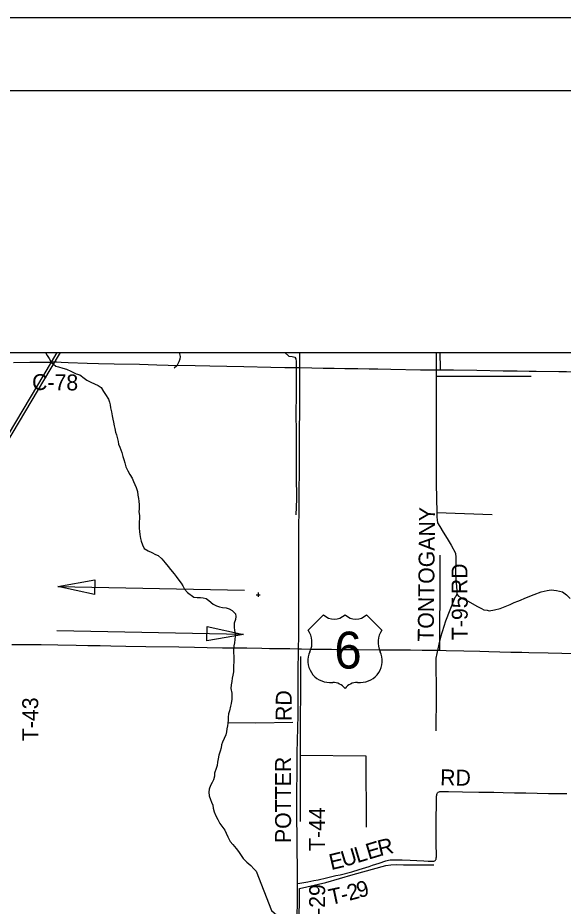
# Model space of a CAD drawing. Extents: x 0 to 680, y 0 to 834.
# Drawn here: x 113.1 to 187.9, y 318.1 to 440 of the extents above; entities that cross this region are included whole.
import ezdxf

# ---------------------------------------------------------------- set-up
doc = ezdxf.new("R2010")
doc.units = 0
for name, color, linetype in [('GM_X_County_Road', 7, 'Continuous'), ('GM_X_County_Road_Text', 7, 'Continuous'), ('GM_X_Interstate_Route', 7, 'Continuous'), ('GM_X_Minor_River', 7, 'Continuous'), ('GM_X_Rail_Line', 7, 'Continuous'), ('GM_X_Township_Road', 7, 'Continuous'), ('GM_X_Township_Road_Text', 7, 'Continuous'), ('GM_X_US_Location', 7, 'Continuous'), ('GM_X_US_Route', 7, 'Continuous'), ('GM_X_US_Shield', 7, 'Continuous'), ('SH_Border', 7, 'Continuous'), ('SH_Cut_Line', 7, 'Continuous'), ('SH_Text', 7, 'Continuous')]:
    doc.layers.add(name, color=color, linetype=linetype)

msp = doc.modelspace()

# ---------------------------------------------------------------- linework, layer by layer
at = {"layer": 'GM_X_County_Road'}
for points in [[(112.52, 392.71), (114.78, 392.73), (116.57, 392.73), (117.16, 392.74), (117.64, 392.77), (117.92, 392.8)], [(117.92, 392.8), (117.99, 392.8), (118.23, 392.8), (118.47, 392.78), (119.07, 392.73), (120.02, 392.69), (122.64, 392.62), (124.19, 392.58), (126.34, 392.54), (129.8, 392.46), (132.19, 392.39), (133.74, 392.35), (137.44, 392.29), (139.47, 392.24), (144.12, 392.15), (147.82, 392.08), (149.73, 392.04), (151.64, 392), (151.82, 392)], [(151.82, 392), (153.43, 391.98), (154.98, 391.94), (156.53, 391.92), (157.96, 391.88), (159.75, 391.87), (161.3, 391.84), (162.49, 391.82), (164.28, 391.79), (168.34, 391.72), (169.65, 391.71), (171.09, 391.7)], [(171.09, 391.7), (172.88, 391.68), (176.1, 391.64), (179.68, 391.58), (181.59, 391.55), (183.26, 391.53), (184.21, 391.51), (187.31, 391.45), (188.39, 391.45), (192.33, 391.36), (193.4, 391.33), (194.47, 391.3), (197.57, 391.2), (199.25, 391.15), (199.76, 391.14)]]:
    msp.add_lwpolyline(points, dxfattribs=at)
at = {"layer": 'GM_X_Interstate_Route'}
msp.add_lwpolyline([(44.69, 394.07), (374.69, 394.07), (374.69, 64.07), (44.69, 64.07)], close=True, dxfattribs=at)
at = {"layer": 'GM_X_Minor_River'}
for p, q in [((145.79, 360.85), (146.37, 360.85)), ((146.08, 361.15), (146.08, 360.56))]:
    msp.add_line(p, q, dxfattribs=at)
for points in [[(116.91, 394.07), (117.12, 393.65), (117.4, 393.25), (117.7, 392.77), (118.32, 392.22), (118.71, 392.09), (119.3, 391.95), (119.79, 391.8), (120.37, 391.51), (120.74, 391.35), (121.13, 391.17), (121.63, 391.01), (122.21, 390.55), (122.58, 390.26), (123.13, 390), (123.65, 389.79), (124.12, 389.53), (124.56, 389.26), (124.89, 388.75), (125.15, 388.32), (125.54, 387.69), (125.71, 387.28), (125.79, 386.9), (125.85, 386.51), (125.96, 385.93), (126.08, 385.4), (126.17, 384.91), (126.24, 384.5), (126.33, 384.03), (126.41, 383.63), (126.53, 383.15), (126.66, 382.78), (126.86, 381.86), (126.95, 381.49), (127.1, 381.11), (127.23, 380.74), (127.38, 380.35), (127.53, 379.81), (127.66, 379.39), (127.79, 378.92), (127.95, 378.39), (128.19, 377.86), (128.48, 377.36), (128.78, 376.84), (129, 376.38), (129.16, 375.97), (129.35, 375.58), (129.52, 375.02), (129.6, 374.49), (129.67, 374.05), (129.72, 373.68), (129.74, 373.16)], [(135.26, 394.07), (135.26, 394.06), (135.39, 393.55), (135.35, 393.18), (135.22, 392.79), (134.95, 392.27), (134.55, 391.94)], [(149.76, 394.07), (150.29, 393.57), (150.74, 393.53), (151.1, 393.46), (151.23, 393.23), (151.3, 392.83), (151.29, 390.82), (151.28, 388), (151.25, 385.97), (151.31, 382.86), (151.31, 379.81), (151.29, 377.2), (151.34, 373.96), (151.26, 371.79)], [(170.52, 394.07), (170.5, 390.84), (170.51, 382.9), (170.51, 376.04), (170.57, 372.13), (170.59, 371.51), (170.62, 371.12), (170.69, 370.69), (171, 370.22), (171.48, 369.45), (172.03, 368.55), (172.58, 367.64), (173.13, 366.57), (173.22, 365.97), (173.13, 363.52), (173.32, 361.45), (173.33, 360.92), (173.18, 360.6), (173.07, 360.45)], [(170.5, 390.84), (177.73, 390.82), (183.52, 390.81)], [(129.74, 373.16), (129.74, 372.63), (129.72, 372.22), (129.79, 371.71), (129.81, 371.27), (129.78, 370.91), (129.76, 370.51), (129.76, 369.99), (129.79, 369.53), (129.86, 369.11), (129.93, 368.58), (130.04, 368.19), (130.22, 367.71), (130.43, 367.2), (130.99, 366.86), (131.49, 366.64), (132.01, 366.38), (132.38, 366.21), (132.86, 365.78), (133.31, 365.23), (133.73, 364.71), (134.08, 364.32), (134.57, 363.72), (134.84, 363.34), (135.21, 362.85), (135.51, 362.44), (135.75, 362.06), (135.96, 361.62), (136.4, 361.14)], [(170.57, 372.13), (178.17, 371.87)], [(136.4, 361.14), (137.24, 360.51), (137.7, 360.48), (138.18, 360.45), (138.56, 360.4), (138.95, 360.34), (139.33, 360.06), (139.89, 359.55), (140.35, 359.31), (140.77, 359.17), (141.18, 359.11), (141.7, 359.05), (142.09, 358.92), (142.51, 358.68), (142.97, 358.23), (143.04, 357.87), (142.98, 357.47), (142.8, 356.95), (142.78, 356.4), (142.86, 355.95), (142.92, 355.55), (142.93, 355.16), (142.89, 354.69), (142.83, 354.27), (142.74, 353.84), (142.7, 353.37), (142.72, 352.87), (142.74, 352.44), (142.73, 351.58), (142.7, 351.15), (142.7, 350.67), (142.68, 350.29), (142.59, 349.79), (142.54, 349.41), (142.46, 348.96), (142.4, 348.49), (142.35, 347.97), (142.47, 347.35), (142.47, 346.9), (142.47, 346.52), (142.36, 345.93), (142.29, 345.54), (142.16, 344.93), (142.03, 344.51), (141.95, 344.07), (141.95, 343.62), (141.92, 343.23), (141.87, 342.85), (141.8, 342.43), (141.72, 342.02), (141.63, 341.64), (141.43, 341.13), (141.18, 340.64), (141.05, 340.24), (140.99, 339.83), (140.86, 339.37), (140.69, 338.82), (140.58, 338.35), (140.52, 337.89), (140.48, 337.43), (140.34, 337), (140.11, 336.39), (140.09, 335.94), (139.97, 335.45), (139.77, 335.07), (139.55, 334.67), (139.38, 334.17), (139.3, 333.74), (139.35, 333.26), (139.56, 332.77), (139.7, 332.39), (139.85, 331.98), (139.93, 331.56), (140.07, 331.07), (140.29, 330.53), (140.55, 329.99), (140.81, 329.47), (141.5, 328.53), (141.7, 328.12), (141.93, 327.63), (142.26, 327.01), (142.59, 326.6), (143.06, 326.05), (143.39, 325.63), (143.67, 325.2), (144.03, 324.65), (144.51, 324.18), (145.06, 323.69), (145.5, 323.26)], [(173.33, 360.92), (173.57, 360.65), (173.87, 360.46), (174.05, 360.35)], [(182.64, 360.38), (183.96, 360.9), (184.92, 361.23), (185.72, 361.42), (186.28, 361.51), (186.99, 361.44), (187.81, 361.24), (188.4, 360.83), (188.89, 360.32)], [(173.07, 360.45), (171.76, 357.2), (171.08, 355.03), (170.86, 354.07), (170.44, 352.13), (170.5, 347.02), (170.44, 342.18)], [(174.05, 360.35), (174.91, 359.95), (176.09, 359.3), (176.74, 358.98), (177.05, 358.79), (177.51, 358.72), (177.75, 358.63), (178.51, 358.76), (179.29, 358.97), (179.98, 359.25), (180.65, 359.51), (181.19, 359.77), (181.71, 359.95), (182.09, 360.11), (182.64, 360.38)], [(151.9, 352.38), (151.83, 338.83), (151.83, 329.73)], [(141.93, 343.34), (145.76, 343.29)], [(145.76, 343.29), (150.86, 343.36)], [(151.83, 338.83), (160.86, 338.73), (160.92, 328.96)], [(145.5, 323.26), (145.81, 322.92), (147.92, 317.54), (151.14, 314.69), (151.74, 314.15), (156.1, 309.86), (160.82, 305.06), (160.75, 297.29), (160.64, 288.68), (160.76, 284.03), (168.14, 284.05), (181.97, 283.96), (186.24, 283.92), (189.11, 285.56)], [(151.7, 315.11), (151.77, 320.54), (155.35, 321.37), (159.11, 322.47), (163.6, 323.68), (164.3, 323.8), (165.1, 323.83), (166.02, 323.79), (168.68, 323.8), (170.17, 323.8)]]:
    msp.add_lwpolyline(points, dxfattribs=at)
at = {"layer": 'GM_X_Rail_Line'}
for points in [[(44.69, 269.33), (51.77, 281.32), (75.21, 320.59), (96.67, 356.59), (117.68, 391.92), (118.96, 394.07)], [(44.69, 271.71), (45.56, 273.26), (46.24, 282.17), (53.4, 286.03), (56.98, 291.07), (66.55, 307.05), (99.13, 361.53), (117.72, 392.75), (118.51, 394.07)]]:
    msp.add_lwpolyline(points, dxfattribs=at)
at = {"layer": 'GM_X_Township_Road'}
for points in [[(151.82, 392), (151.82, 392.31), (151.81, 393.62), (151.8, 394.07)], [(171.09, 391.7), (171.09, 391.87), (171.09, 392.13), (171.08, 392.63), (171.07, 393.28), (171.07, 394.06), (171.07, 394.07)], [(151.62, 353.43), (151.63, 353.64), (151.65, 354.95), (151.65, 357.1), (151.65, 359.72), (151.66, 362.71), (151.67, 364.38), (151.67, 367.12), (151.67, 367.96), (151.68, 370.46), (151.69, 372.02), (151.72, 374.88), (151.74, 377.98), (151.75, 379.77), (151.76, 383.12), (151.78, 386.34), (151.79, 387.41), (151.78, 388.25), (151.8, 390.05), (151.82, 392)], [(171, 353.22), (171, 353.95), (171, 355.87), (171.01, 357.78), (171.03, 359.57), (171.04, 361), (171.04, 362.2), (171.05, 363.99), (171.05, 365.07), (171.05, 366.26)], [(151.48, 321.24), (151.47, 322.25), (151.47, 323.09), (151.47, 323.68), (151.46, 324.16), (151.44, 325.11), (151.43, 325.59), (151.42, 327.14), (151.41, 330.72), (151.41, 333.23), (151.44, 337.05), (151.45, 339.19), (151.48, 340.87), (151.55, 344.33), (151.56, 347.19), (151.59, 351.13), (151.6, 352.44), (151.62, 353.43)], [(151.48, 321.24), (151.78, 321.27), (152.09, 321.33), (152.9, 321.47), (153.72, 321.63), (154.3, 321.75), (155.47, 322.01), (156.75, 322.31), (157.33, 322.43), (158.95, 322.84), (159.92, 323.14), (161.32, 323.58), (161.78, 323.74), (162.69, 324.04), (163.6, 324.33), (163.94, 324.42), (164.17, 324.47), (164.41, 324.5), (164.77, 324.5), (165.25, 324.49), (165.84, 324.46), (166.92, 324.41), (167.87, 324.37), (168.82, 324.33), (169.39, 324.31), (169.86, 324.29), (170.02, 324.29), (170.17, 324.31), (170.3, 324.34), (170.38, 324.39), (170.43, 324.45), (170.47, 324.51), (170.49, 324.55), (170.51, 324.63), (170.52, 324.75), (170.53, 324.87), (170.53, 325.03), (170.53, 325.23), (170.51, 326.54), (170.5, 327.57), (170.5, 328.67), (170.52, 329.78), (170.53, 332.48), (170.54, 332.86), (170.55, 333.23), (170.57, 333.35), (170.6, 333.46), (170.64, 333.57), (170.7, 333.67), (170.78, 333.76), (170.89, 333.82), (171, 333.85), (171.12, 333.86), (172.19, 333.83), (174.1, 333.79), (176.37, 333.77), (178.4, 333.74), (179.71, 333.72), (181.26, 333.69), (182.82, 333.67), (185.91, 333.59), (187.05, 333.58), (188.43, 333.58)], [(151.43, 315.1), (151.44, 316.04), (151.46, 319.39), (151.48, 320.82), (151.48, 321.24)]]:
    msp.add_lwpolyline(points, dxfattribs=at)
at = {"layer": 'GM_X_US_Route'}
msp.add_lwpolyline([(112.31, 354.04), (113.96, 354.04), (116.3, 354.02), (118.61, 353.98), (121.12, 353.93), (122.74, 353.9), (124.39, 353.87), (125.89, 353.85), (127.94, 353.81), (130.66, 353.75), (135.22, 353.68), (137.37, 353.64), (139.09, 353.61), (141.19, 353.58), (144.51, 353.54), (146.61, 353.5), (147.64, 353.49), (148.76, 353.48), (150.43, 353.45), (151.62, 353.43), (152.03, 353.42), (153.29, 353.4), (154.56, 353.37), (156.16, 353.36), (157.16, 353.35), (158.43, 353.34), (159.79, 353.34), (162.75, 353.31), (164.8, 353.28), (165.83, 353.27), (167, 353.27), (168.6, 353.25), (171, 353.22), (171.87, 353.21), (174.31, 353.16), (176.51, 353.1), (177.71, 353.07), (179.24, 353.02), (180.72, 352.99), (182.27, 352.96), (183.2, 352.94), (185.88, 352.87), (187.76, 352.82), (189.38, 352.77)], dxfattribs=at)
at = {"layer": 'GM_X_US_Shield'}
for p, q in [((155.05, 358.1), (152.94, 355.99)), ((163.06, 355.99), (160.95, 358.1)), ((155.89, 348.82), (156.31, 348.82)), ((159.69, 348.82), (160.11, 348.82))]:
    msp.add_line(p, q, dxfattribs=at)
for centre, radius, start, end in [((156.52, 359.61), 2.11, 225.573, 314.427), ((159.48, 359.61), 2.11, 225.573, 314.427), ((150.52, 354.3), 2.95, 334.5471, 35.0009), ((165.48, 354.3), 2.95, 144.9991, 205.4529), ((155.86, 351.77), 2.95, 154.8319, 270.6383), ((160.14, 351.77), 2.95, 269.3617, 25.1681), ((156.31, 346.71), 2.11, 36.8699, 90), ((159.69, 346.71), 2.11, 90, 143.1301)]:
    msp.add_arc(centre, radius, start, end, dxfattribs=at)
at = {"layer": 'SH_Border'}
msp.add_lwpolyline([(30, 430), (670, 430), (670, 10), (30, 10)], close=True, dxfattribs=at)
at = {"layer": 'SH_Cut_Line'}
msp.add_lwpolyline([(0, 0), (680, 0), (680, 440), (0, 440)], close=True, dxfattribs=at)
at = {"layer": 'SH_Text'}
for p, q in [((118.6, 361.96), (144.22, 361.48)), ((144.09, 355.41), (118.46, 355.89))]:
    msp.add_line(p, q, dxfattribs=at)
for points in [[(123.62, 360.86), (118.6, 361.96), (123.66, 362.87)], [(139.07, 356.51), (144.09, 355.41), (139.03, 354.5)]]:
    msp.add_lwpolyline(points, close=True, dxfattribs=at)

# ---------------------------------------------------------------- texts
at = {"layer": 'GM_X_County_Road_Text'}
msp.add_text('C-78', height=2.182, rotation=359.3864, dxfattribs=at).set_placement((115.06, 388.94))
at = {"layer": 'GM_X_Township_Road_Text'}
for s, height, rotation, p in [('TONTOGANY', 2.182, 89.3435, (170.15, 354.39)), ('RD', 2.182, 90, (174.79, 360.92)), ('T-95', 2.182, 90, (174.82, 354.62)), ('RD', 2.182, 89.5002, (150.66, 343.52)), ('T-43', 2.182, 90, (115.91, 340.76)), ('POTTER', 2.182, 90, (150.59, 326.78)), ('RD', 2.182, 359.0241, (171.03, 334.71)), ('T-44', 2.182, 90, (155.24, 325.69)), ('E', 2.18, 16.7542, (161.23, 324.49)), ('R', 2.18, 13.5004, (162.76, 324.96)), ('E', 2.18, 13.3149, (156.1, 323.06)), ('U', 2.18, 16.793, (157.83, 323.47)), ('L', 2.18, 16.7678, (159.67, 324.02)), ('T-29', 2.182, 89.6619, (155.24, 315.13)), ('T', 2.18, 12.1546, (156.01, 318.27)), ('2', 2.18, 14.9251, (158.58, 318.85)), ('9', 2.18, 15.8897, (159.92, 319.21)), ('-', 2.18, 13.2771, (157.65, 318.63))]:
    msp.add_text(s, height=height, rotation=rotation, dxfattribs=at).set_placement(p)
at = {"layer": 'GM_X_US_Location'}
msp.add_text('6', height=0.00727, rotation=0, dxfattribs=at).set_placement((158.65, 352.63))
at = {"layer": 'GM_X_US_Shield'}
msp.add_text('6', height=5.06, dxfattribs=at).set_placement((156.53, 350.72))

doc.saveas('drawing.dxf')
